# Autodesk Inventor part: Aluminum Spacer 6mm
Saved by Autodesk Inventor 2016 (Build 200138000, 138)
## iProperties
Created: 2015-11
Part Number: Aluminum Spacer 6mm
Material: Generic
Document SubType Name: Modeling
Designer: John
Density: 1 g/cm^3
Appearance: Default
Author: John
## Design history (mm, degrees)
feature "SOLID1"
body "Solid1"
